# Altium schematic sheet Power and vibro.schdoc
size 297 x 209 mm; Symbol: Drawing-Symbol_A4; @Project Name: Hưhwwuey; @Page Count: 9; @Update Date: 2026-10-18; @Create Date: 2026-10-18; @Schematic Name: Schematic1; @Page No: 9; @Page Name: P1; Company: EasyEDA.com; Version: V1.0; Page Size: A4; Device: Drawing-Symbol_A4; @Create Time: 21:32:22; @Update Time: 21:32:22; Border: 1; Width: 1170; Height: 825; Region Start: 1; X Region Count: 6; Y Region Count: 4; Blade Width: 10; Title Block Position: 3; @Board Name: Board1
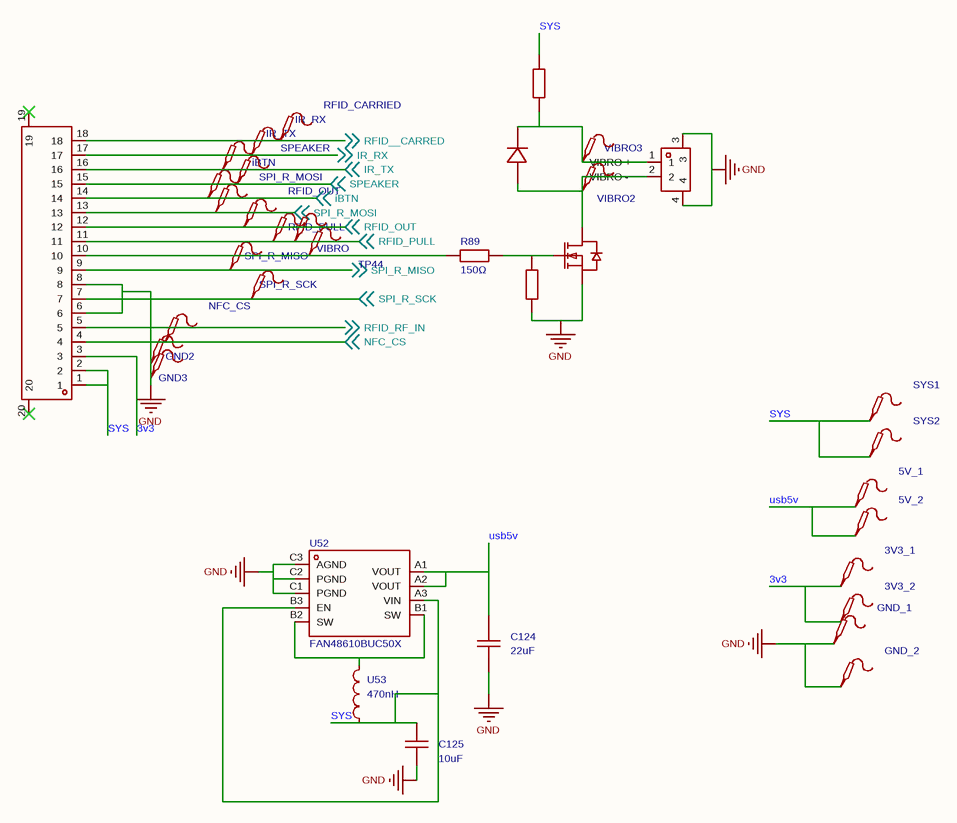
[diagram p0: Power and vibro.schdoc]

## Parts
C124  22uF  [C0603]
C125  10uF  [C0402]
FPC3  1.0K-LS-2PWB-TW  [FPC-SMD_1.0K-LS-2PWB-TW]  (value not drawn)
Q7  DMN2058UW-7  [SOT-323-3_L2.2-W1.3-P1.30-LS2.1-BR]  (value not drawn)
R89  150Ω  [R0402]
R90  10K  [R0402]  (value not drawn)
R92  22Ω  [R0805]  (value not drawn)
TP33  NFC_CS  [Test-Point-0.5mm]
TP34  GND2  [Test-Point-0.5mm]
TP35  GND3  [Test-Point-0.5mm]
TP36  SPI_R_SCK  [Test-Point-0.5mm]
TP37  SPI_R_MISO  [Test-Point-0.5mm]
TP38  VIBRO  [Test-Point-0.5mm]
TP39  VIBRO2  [Test-Point-0.5mm]
TP40  VIBRO3  [Test-Point-0.5mm]
TP41  RFID_PULL  [Test-Point-0.5mm]
TP42  RFID_OUT  [Test-Point-0.5mm]
TP43  SPI_R_MOSI  [Test-Point-0.5mm]
TP44  (no value)  [Test-Point-0.5mm]
TP45  iBTN  [Test-Point-0.5mm]
TP46  SPEAKER  [Test-Point-0.5mm]
TP47  IR_TX  [Test-Point-0.5mm]
TP48  IR_RX  [Test-Point-0.5mm]
TP49  RFID_CARRIED  [Test-Point-0.5mm]
TP50  GND_2  [Test-Point-0.5mm]
TP51  GND_1  [Test-Point-0.5mm]
TP52  3V3_2  [Test-Point-0.5mm]
TP53  3V3_1  [Test-Point-0.5mm]
TP54  5V_2  [Test-Point-0.5mm]
TP55  5V_1  [Test-Point-0.5mm]
TP56  SYS2  [Test-Point-0.5mm]
TP57  SYS1  [Test-Point-0.5mm]
U50  FH34SRJ-18S-0.5SH(50)  [FFC-SMD_18P-P0.50_FH34SRJ-18S-0.5SH]  (value not drawn)
U51  1N4148X-TP  [SOD-523F_L1.2-W0.8-LS1.7-RD]  (value not drawn)
U52  FAN48610BUC50X  [WLCSP-9_L1.2-W1.2-R3-C3-P0.40-BL]
U53  470nH  [L0806]

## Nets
GND: C124.1 C125.1 FPC3.3 FPC3.4 Q7.2(S) R90.1 TP34.1 TP35.1 TP50.1 TP51.1 U50.6 U50.8 U52.C1(PGND) U52.C2(PGND) U52.C3(AGND)
3v3: TP52.1 TP53.1 U50.3
iBTN: TP45.1 U50.14 ; off-sheet iBTN
IR_RX: TP48.1 U50.17 ; off-sheet IR_RX
IR_TX: TP47.1 U50.16 ; off-sheet IR_TX
NFC_CS: TP33.1 U50.4 ; off-sheet NFC_CS
RFID__CARRED: TP49.1 U50.18 ; off-sheet RFID__CARRED
RFID_OUT: TP42.1 U50.12 ; off-sheet RFID_OUT
RFID_PULL: TP41.1 TP44.1 U50.11 ; off-sheet RFID_PULL
RFID_RF_IN: U50.5 ; off-sheet RFID_RF_IN
SPEAKER: TP46.1 U50.15 ; off-sheet SPEAKER
SPI_R_MISO: TP37.1 U50.9 ; off-sheet SPI_R_MISO
SPI_R_MOSI: TP43.1 U50.13 ; off-sheet SPI_R_MOSI
SPI_R_SCK: TP36.1 U50.7 ; off-sheet SPI_R_SCK
SYS: C125.2 R92.2 TP56.1 TP57.1 U50.1 U50.2 U52.A3(VIN) U52.B3(EN) U53.1
usb5v: C124.2 TP54.1 TP55.1 U52.A1(VOUT) U52.A2(VOUT)
NetFPC3_1: FPC3.1 R92.1 TP40.1 U51.1(C)
NetFPC3_2: FPC3.2 Q7.3(D) TP39.1 U51.2(A)
NetQ7_1: Q7.1(G) R89.2 R90.2
NetR89_1: R89.1 TP38.1 U50.10
NetU52_B1: U52.B1(SW) U52.B2(SW) U53.2

Not connected (* = marked no-connect by the designer): U50 19* 20*

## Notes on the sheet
- VIBRO -
- (near TP40) VIBRO +

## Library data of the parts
C124 = FCC0603X226M100CT: Capacitance:22uF Tolerance:±20% Tolerance:±20% Voltage Rating:10V Temperature Coefficient:X5R Operating Temperature:-55℃~+85℃ Operating Temperature:-55℃~+85℃; Manufacturer: FOJAN(富捷); AddInBom: yes; ModelId: 624118aa3cc7497086c383c2d72e08520819f05c4eef4c71ace90d822a990e87; ModelName: C0603_L1.6-W0.8-H0.8; ModelTransform: 62.992,31.496,0,0,0,0,0,0,0; Tolerance: ±20%; Voltage Rating: 10V; Temperature Coefficient: X5R
C125 = CL05A106MQ5NUNC: Capacitance:10uF Tolerance:±20% Tolerance:±20% Voltage Rating:6.3V Temperature Coefficient:X5R; Manufacturer: SAMSUNG(三星); AddInBom: yes; ModelId: b7d13df3e9464d7a99d0651d1a5b4d570819f05c4eef4c71ace90d822a990e87; ModelName: C0402_L1.0-W0.5-H0.5; ModelTransform: 39.37,19.685,0,0,0,0,0,0,0; Tolerance: ±20%; Voltage Rating: 6.3V; Temperature Coefficient: X5R
FPC3 = 1.0K-LS-2PWB-TW: Locking Feature:Slide Lock Contact Type:Top Contact Number of Contacts:2P Pitch:1mm Mounting Type:Surface Mount, Right Angle FFC, FCB Thickness:0.3mm FFC, FCB Thickness:0.3mm Height Above Board:2mm Contact Material:Phosphor bronze Contact Plating:Tin Oper; Manufacturer: GUOCONN(国连); AddInBom: yes; Number of Contacts: 2P; Pitch: 1mm; FFC, FCB Thickness: 0.3mm; Rated Voltage (Max): 50V; Current Rating (Max): 400mA
Q7 = DMN2058UW-7: Number:1 N-channel Drain to Source Voltage:20V Current - Continuous Drain(Id):3.5A RDS(on):31.5mΩ@10V Pd - Power Dissipation:0.7mW Gate Threshold Voltage (Vgs(th)):1.2V Gate Charge(Qg):7.7nC@10V Input Capacitance(Ciss):281pF Reverse Transfer Capacitance (; Manufacturer: DIODES(美台); 3D Model: 00b47c5ba4b548a981fce2870442aba00819f05c4eef4c71ace90d822a990e87; 3D Model Transform: 78.74,82.677,0,90,0,0,-0.001,-0.001,0; Drain to Source Voltage: 20V; Current - Continuous Drain(Id): 3.5A; Pd - Power Dissipation: 0.7mW; Gate Threshold Voltage (Vgs(th)): 1.2V; Input Capacitance(Ciss): 281pF; Reverse Transfer Capacitance (Crss@Vds): 39pF; Output Capacitance(Coss): 50pF; AddInBom: yes; ModelName: SOT-323-3_L2.0-W1.3-H1.0-LS2.1-P1.30
R89 = RC0402JR-07150RL: Type:Thick Film Resistor Resistance:150Ω Tolerance:±5% Tolerance:±5% Power(Watts):62.5mW Voltage-Supply(Max):50V Temperature Coefficient:±100ppm/℃ Temperature Coefficient:±100ppm/℃ Operating Temperature:-55℃~+155℃ Operating Temperature:-55℃~+155℃; Manufacturer: YAGEO(国巨); 3D Model: efdecb7dae4442949d28eecaf748420f0819f05c4eef4c71ace90d822a990e87; 3D Model Transform: 39.37,19.685,0,0,0,0,0,0,0; Tolerance: ±5%; Power(Watts): 62.5mW; Voltage-Supply(Max): 50V; AddInBom: yes; ModelName: R0402_L1.0-W0.5-H0.4
R90 = Res_0402: Symbol: Res; 3D Model: efdecb7dae4442949d28eecaf748420f0819f05c4eef4c71ace90d822a990e87; 3D Model Transform: 39.37,19.685,0,0,0,0,0,0,0; ConvertToPcb: yes; ModelName: R0402_L1.0-W0.5-H0.4
R92 = WR08X220JTL: Type:Thick Film Resistor Resistance:22Ω Tolerance:±5% Tolerance:±5% Power(Watts):125mW Voltage-Supply(Max):150V Temperature Coefficient:±100ppm/℃ Temperature Coefficient:±100ppm/℃ Operating Temperature:-55℃~+155℃ Operating Temperature:-55℃~+155℃; Manufacturer: Walsin(华新科); AddInBom: yes; ModelId: b83c7c5430874b8eb2319a65d94334290819f05c4eef4c71ace90d822a990e87; ModelName: R0805_L2.0-W1.3-H0.6; ModelTransform: 78.74,51.181,0,0,0,0,0,-0.0005,0; Tolerance: ±5%; Power(Watts): 125mW; Voltage-Supply(Max): 150V
TP33-TP57 = Test-Point: Test Point 测试点; AddInBom: yes
U50 = FH34SRJ-18S-0.5SH(50): Locking Feature:Flip-top (front insert,rear flip) Contact Type:Double-Sided Contacts, Top and Bottom Entry Number of Contacts:18P Pitch:0.5mm Mounting Type:Surface Mount, Right Angle FFC, FCB Thickness:0.3mm FFC, FCB Thickness:0.3mm Height Above Board:1mm; Manufacturer: HRS(广濑); 3D Model: ebf172207cb640f5a031a3b119151af90819f05c4eef4c71ace90d822a990e87; 3D Model Transform: 433.464,149.606,0,0,0,0,0,5.551,0; Number of Contacts: 18P; Pitch: 0.5mm; FFC, FCB Thickness: 0.3mm; Rated Voltage (Max): 50V; Current Rating (Max): 500mA; FPC/FFC Lock: Without buckle; Forward Foot / Back Foot: No polarity; AddInBom: yes
U51 = 1N4148X-TP: Diode Configuration:1 Independent Pd - Power Dissipation:200mW Current - Rectified:150mA Voltage - DC Reverse(Vr):75V Voltage - Forward(Vf@If):1.25V@150mA Non-Repetitive Peak Forward Surge Current:2A Reverse Leakage Current (Ir):1uA@75V Reverse Recovery T; Manufacturer: MCC(美微科); 3D Model: 53f385f253c24b16903baed56d7fb4c80819f05c4eef4c71ace90d822a990e87; 3D Model Transform: 62.992,31.496,0,0,0,0,-0.005,0.16,0; Pd - Power Dissipation: 200mW; Current - Rectified: 150mA; Voltage - DC Reverse(Vr): 75V; Non-Repetitive Peak Forward Surge Current: 2A; Reverse Recovery Time (trr): 4ns; Operating Junction Temperature Range: -65℃~+150℃; AddInBom: yes; ModelName: SOD-523F_L1.2-W0.8-H0.6-LS1.6
U52 = FAN48610BUC50X: Function:Boost Voltage - Supply:2.5V~4.8V Voltage - Supply:2.5V~4.8V Output Voltage:5V Output Voltage:5V Output Current:1.5A Frequency - Switching:2MHz~3MHz Frequency - Switching:2MHz~3MHz Operating Temperature:-40℃~+85℃@(TA) Operating Temperature:-40℃~+8; Manufacturer: onsemi(安森美); AddInBom: yes; ModelId: 81fc2f58c7644bb6a2ca155dfaf570000819f05c4eef4c71ace90d822a990e87; ModelName: WLCSP-9_L1.2-W1.2-H0.6-R3-C3-P0.40-BL; ModelTransform: 47.83455,47.83455,0,0,0,0,-0.002,0.004,0; Function: Boost; Output Voltage: 5V; Output Current: 1.5A; Number of Outputs: 1; Quiescent Current: 85uA; Switch tube (built-in/external): Built-in; Output Type: Fixed
U53 = DFE201610E-R47M=P2: Inductance:470nH Tolerance:±20% Tolerance:±20% Current Rating:3.6A Current - Saturation(Isat):4.8A DC Resistance(DCR):32mΩ Ratings:-; Manufacturer: muRata(村田); AddInBom: yes; ModelId: 50126e67425b4d0e857ac4e361b69b090819f05c4eef4c71ace90d822a990e87; ModelName: L0806_L2.0-W1.6-H1.0; ModelTransform: 78.74,62.992,0,0,0,0,0,0,0; Tolerance: ±20%; Current Rating: 3.6A; Current - Saturation(Isat): 4.8A; DC Resistance(DCR): 32mΩ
